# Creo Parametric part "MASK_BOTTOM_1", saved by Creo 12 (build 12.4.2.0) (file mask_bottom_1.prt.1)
Units: Custom; MM, KILOGRAM, SECS

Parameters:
  PTC_WM_ITERATION = "0"
  PTC_WM_VERSION = "-.0"
  PTC_WM_LIFECYCLE_STATE = "In Work"
  PTC_WM_LIFECYCLE = "MO_CADDocument"
  PTC_WM_CREATED_BY = "Maximilian Roepper (Z0017RMS: MO)"
  PTC_WM_CREATED_ON = "18-Sep-26 11:36:42 AM"
  PTC_WM_MODIFIED_BY = "Maximilian Roepper (Z0017RMS: MO)"
  PTC_WM_MODIFIED_ON = "18-Sep-26 11:36:46 AM"
  PDMLINKNUMBER = "PDM000071454788"
  PTC_WM_NAME = "mask_bottom_1.prt"
  PTC_WM_NUMBER = "PDM000071454788"

Other parameters: WEIGHT, WEIGHT_FACTOR, WEIGHT_ADD, _MASS_TEMP, _DIFF_TEMP, MC_ERRORS, SUPPLIER

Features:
  1. coordinate system
  2. datum plane "PRT_YZ"
  3. datum plane "PRT_XY"
  4. datum plane "PRT_XZ"
  5. coordinate system
  6. datum axis
  7. datum axis
  8. datum axis
  9. coordinate system
  10. imported feature
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
Other named items: PRT, SIEMENS_MO, DRW_VIEW_ORG, PRT_X, PRT_Y, PRT_Z, CS0, ROUGH_GROB

Layers: 00_STD_CSYS-KSYS, 01_STD_PLANES-EBENEN, 02_STD_AXES-ACHSEN, 03_STD_CSYS-KSYS, 24_IMPORT_FEAT-IMPORT_KE

Surfaces: 182 plane, 44 cylinder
